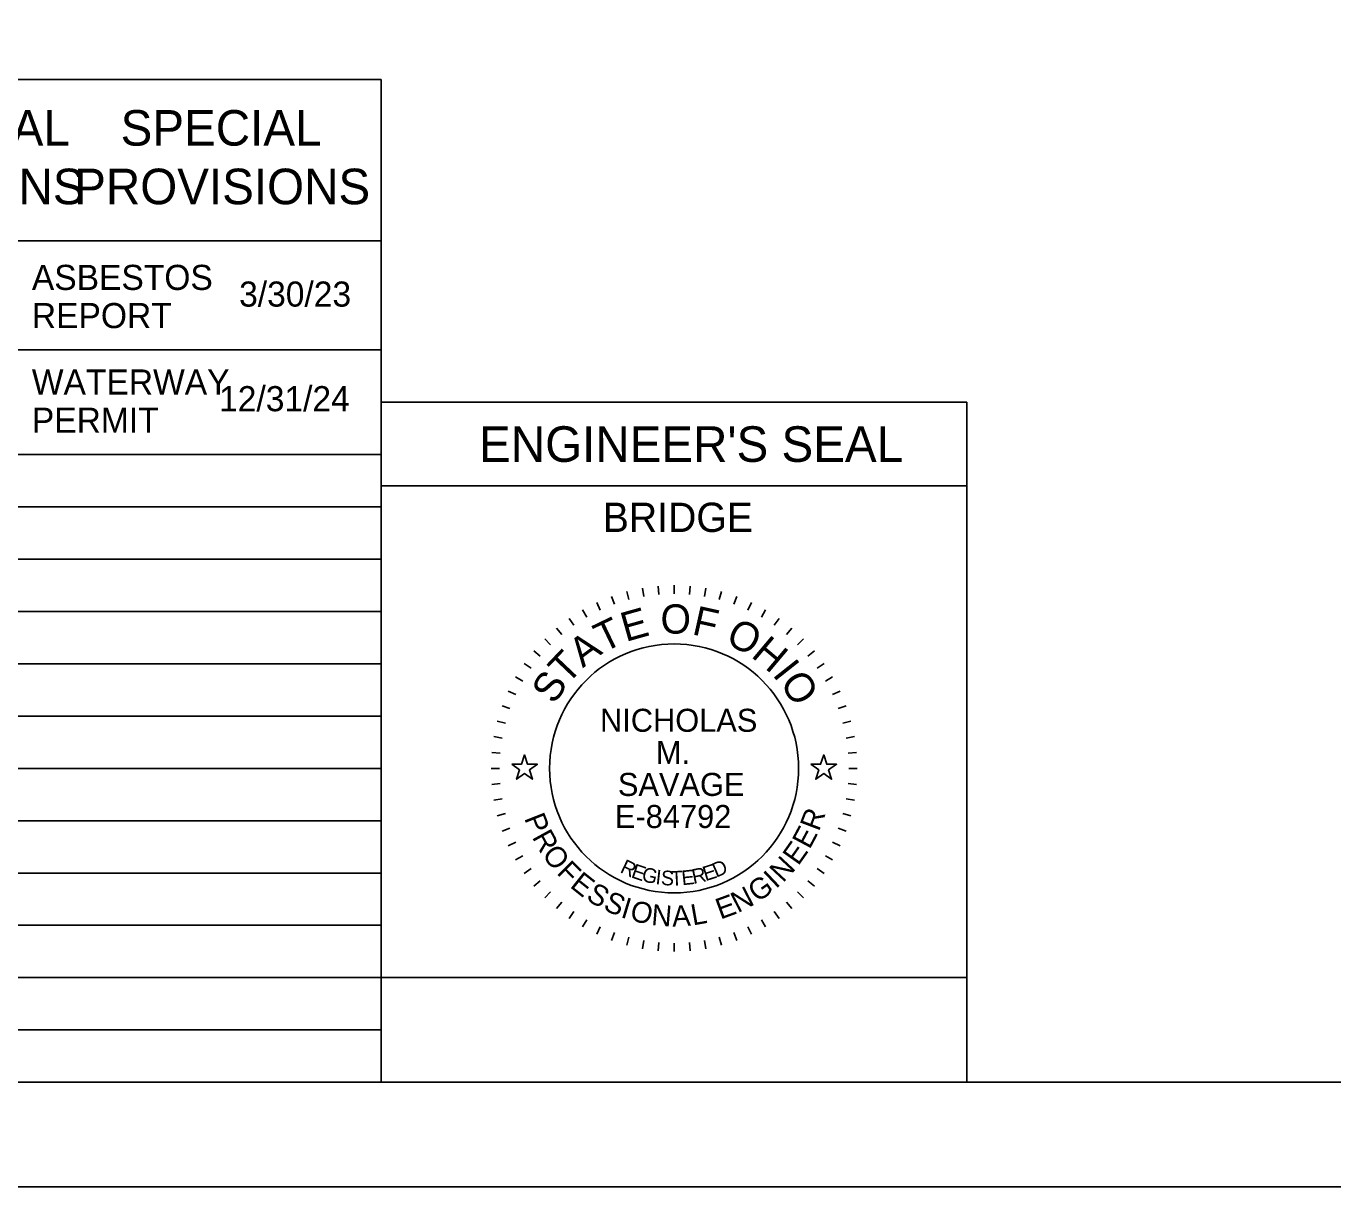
# Model space of a CAD drawing. Extents: x 0 to 34, y 0 to 22.
# Drawn here: x 21.9 to 28.15, y 0 to 5.55 of the extents above; entities that cross this region are included whole.
import ezdxf

# ---------------------------------------------------------------- set-up
doc = ezdxf.new("R2010")
doc.units = 0
for name, color, linetype in [('SH_Border', 7, 'Continuous'), ('SH_Cut_Line', 7, 'Continuous'), ('SH_Data', 7, 'Continuous'), ('SH_Seal', 7, 'Continuous'), ('SH_Text', 7, 'Continuous')]:
    doc.layers.add(name, color=color, linetype=linetype)

msp = doc.modelspace()

# ---------------------------------------------------------------- linework, layer by layer
at = {"layer": 'SH_Border'}
msp.add_lwpolyline([(1.5, 21.5), (33.5, 21.5), (33.5, 0.5), (1.5, 0.5)], close=True, dxfattribs=at)
at = {"layer": 'SH_Cut_Line'}
msp.add_lwpolyline([(0, 0), (34, 0), (34, 22), (0, 22)], close=True, dxfattribs=at)
at = {"layer": 'SH_Data'}
for p, q in [((10.15, 5.2917), (23.6, 5.2917)), ((23.6, 0.5), (23.6, 5.2917)), ((10.15, 4.5209), (23.6, 4.5209)), ((10.15, 4), (23.6, 4)), ((23.6, 0.5), (23.6, 3.75)), ((23.6, 3.75), (26.4, 3.75)), ((26.4, 3.75), (26.4, 0.5)), ((10.15, 3.5), (23.6, 3.5)), ((23.6, 3.35), (26.4, 3.35)), ((10.15, 3.25), (23.6, 3.25)), ((10.15, 3), (23.6, 3)), ((10.15, 2.75), (23.6, 2.75)), ((10.15, 2.5), (23.6, 2.5)), ((10.15, 2.25), (23.6, 2.25)), ((10.15, 2), (23.6, 2)), ((10.15, 1.75), (23.6, 1.75)), ((10.15, 1.5), (23.6, 1.5)), ((10.15, 1.25), (23.6, 1.25)), ((10.15, 1), (23.6, 1)), ((10.15, 0.75), (23.6, 0.75)), ((23.6, 0.5), (26.4, 0.5))]:
    msp.add_line(p, q, dxfattribs=at)
msp.add_lwpolyline([(23.6, 0.5), (23.6, 1), (26.4, 1), (26.4, 0.5)], close=True, dxfattribs=at)
at = {"layer": 'SH_Seal'}
for p, q in [((25, 2.875), (25, 2.835)), ((24.7007, 2.8222), (24.7144, 2.7846)), ((24.7735, 2.8452), (24.7839, 2.8065)), ((24.8481, 2.8617), (24.855, 2.8223)), ((24.9237, 2.8717), (24.9272, 2.8318)), ((25.0763, 2.8717), (25.0728, 2.8318)), ((25.1519, 2.8617), (25.145, 2.8223)), ((25.2265, 2.8452), (25.2161, 2.8065)), ((25.2993, 2.8222), (25.2856, 2.7846)), ((24.5625, 2.7578), (24.5825, 2.7231)), ((24.6302, 2.793), (24.6471, 2.7568)), ((25.3698, 2.793), (25.3529, 2.7568)), ((25.4375, 2.7578), (25.4175, 2.7231)), ((24.4981, 2.7168), (24.5211, 2.684)), ((25.5019, 2.7168), (25.4789, 2.684)), ((24.4376, 2.6703), (24.4633, 2.6396)), ((25.5624, 2.6703), (25.5367, 2.6396)), ((24.3297, 2.5624), (24.3604, 2.5367)), ((24.3813, 2.6187), (24.4096, 2.5904)), ((25.6187, 2.6187), (25.5904, 2.5904)), ((25.6703, 2.5624), (25.6396, 2.5367)), ((24.2832, 2.5019), (24.316, 2.4789)), ((25.7168, 2.5019), (25.684, 2.4789)), ((24.2422, 2.4375), (24.2769, 2.4175)), ((25.7578, 2.4375), (25.7231, 2.4175)), ((24.207, 2.3698), (24.2432, 2.3529)), ((25.793, 2.3698), (25.7568, 2.3529)), ((24.1778, 2.2993), (24.2154, 2.2856)), ((25.8222, 2.2993), (25.7846, 2.2856)), ((24.1548, 2.2265), (24.1935, 2.2161)), ((25.8452, 2.2265), (25.8065, 2.2161)), ((24.1383, 2.1519), (24.1777, 2.145)), ((25.8617, 2.1519), (25.8223, 2.145)), ((24.1283, 2.0763), (24.1682, 2.0728)), ((25.8717, 2.0763), (25.8318, 2.0728)), ((24.125, 2), (24.165, 2)), ((25.875, 2), (25.835, 2)), ((24.1283, 1.9237), (24.1682, 1.9272)), ((25.8717, 1.9237), (25.8318, 1.9272)), ((24.1383, 1.8481), (24.1777, 1.855)), ((25.8617, 1.8481), (25.8223, 1.855)), ((24.1548, 1.7735), (24.1935, 1.7839)), ((25.8452, 1.7735), (25.8065, 1.7839)), ((24.1778, 1.7007), (24.2154, 1.7144)), ((25.8222, 1.7007), (25.7846, 1.7144)), ((24.207, 1.6302), (24.2432, 1.6471)), ((25.793, 1.6302), (25.7568, 1.6471)), ((24.2422, 1.5625), (24.2769, 1.5825)), ((25.7578, 1.5625), (25.7231, 1.5825)), ((24.2832, 1.4981), (24.316, 1.5211)), ((25.7168, 1.4981), (25.684, 1.5211)), ((24.3297, 1.4376), (24.3604, 1.4633)), ((25.6703, 1.4376), (25.6396, 1.4633)), ((24.3813, 1.3813), (24.4096, 1.4096)), ((25.6187, 1.3813), (25.5904, 1.4096)), ((24.4376, 1.3297), (24.4633, 1.3604)), ((24.4981, 1.2832), (24.5211, 1.316)), ((25.5019, 1.2832), (25.4789, 1.316)), ((25.5624, 1.3297), (25.5367, 1.3604)), ((24.5625, 1.2422), (24.5825, 1.2769)), ((25.4375, 1.2422), (25.4175, 1.2769)), ((24.6302, 1.207), (24.6471, 1.2432)), ((24.7007, 1.1778), (24.7144, 1.2154)), ((24.7735, 1.1548), (24.7839, 1.1935)), ((25.2265, 1.1548), (25.2161, 1.1935)), ((25.2993, 1.1778), (25.2856, 1.2154)), ((25.3698, 1.207), (25.3529, 1.2432)), ((24.8481, 1.1383), (24.855, 1.1777)), ((24.9237, 1.1283), (24.9272, 1.1682)), ((25, 1.125), (25, 1.165)), ((25.0763, 1.1283), (25.0728, 1.1682)), ((25.1519, 1.1383), (25.145, 1.1777))]:
    msp.add_line(p, q, dxfattribs=at)
for points in [[(24.2236, 2.02), (24.2705, 2.02), (24.285, 2.0645), (24.2995, 2.02), (24.3464, 2.02), (24.3085, 1.9924), (24.323, 1.9478), (24.285, 1.9754), (24.247, 1.9478), (24.2615, 1.9924)], [(25.6536, 2.02), (25.7005, 2.02), (25.715, 2.0645), (25.7295, 2.02), (25.7764, 2.02), (25.7385, 1.9924), (25.753, 1.9478), (25.715, 1.9754), (25.677, 1.9478), (25.6915, 1.9924)]]:
    msp.add_lwpolyline(points, close=True, dxfattribs=at)
msp.add_circle((25, 2), 0.595, dxfattribs=at)

# ---------------------------------------------------------------- texts
at = {"layer": 'SH_Data'}
for s, height, p in [("ENGINEER'S SEAL", 0.17, (24.0676, 3.465)), ('BRIDGE', 0.14, (24.659, 3.13))]:
    msp.add_text(s, height=height, dxfattribs=at).set_placement(p)
at = {"layer": 'SH_Seal'}
for s, height, rotation, p in [('E', 0.14, 15.75706, (24.7684, 2.6038)), ('O', 0.14, 359.78119, (24.9347, 2.6443)), ('F', 0.14, 347.43619, (25.0811, 2.6417)), ('T', 0.14, 25.71674, (24.6616, 2.5518)), ('O', 0.14, 332.25863, (25.2398, 2.6015)), ('A', 0.14, 36.47472, (24.5634, 2.4781)), ('H', 0.14, 319.91363, (25.3632, 2.5361)), ('T', 0.14, 46.4344, (24.4883, 2.3964)), ('I', 0.14, 308.36695, (25.4665, 2.4483)), ('S', 0.14, 57.19238, (24.4281, 2.3014)), ('O', 0.14, 303.14906, (25.5021, 2.4089)), ('P', 0.1, 291.49398, (24.2823, 1.7621)), ('R', 0.1, 69.23216, (25.6919, 1.6954)), ('R', 0.1, 298.73106, (24.319, 1.6717)), ('E', 0.1, 61.99508, (25.6476, 1.6098)), ('O', 0.1, 306.46664, (24.3655, 1.5883)), ('E', 0.1, 54.75801, (25.5933, 1.5314)), ('R', 0.07, 334.48695, (24.7375, 1.5051)), ('N', 0.1, 47.02243, (25.5202, 1.4508)), ('F', 0.1, 314.7068, (24.4343, 1.4983)), ('E', 0.1, 321.43929, (24.4978, 1.4348)), ('E', 0.07, 341.03996, (24.7906, 1.4801)), ('G', 0.07, 347.47515, (24.8414, 1.4618)), ('I', 0.07, 353.78581, (24.9091, 1.4468)), ('S', 0.07, 356.89262, (24.9358, 1.4429)), ('T', 0.07, 3.00609, (24.9857, 1.4387)), ('E', 0.07, 6.01169, (25.0389, 1.4412)), ('R', 0.07, 11.91844, (25.0925, 1.4474)), ('E', 0.07, 17.68363, (25.1498, 1.4602)), ('D', 0.07, 23.30524, (25.201, 1.477)), ('I', 0.1, 43.28703, (25.4868, 1.4214)), ('S', 0.1, 328.67637, (24.5743, 1.3752)), ('G', 0.1, 35.04687, (25.3981, 1.357)), ('S', 0.1, 335.91345, (24.6564, 1.3266)), ('I', 0.1, 343.15053, (24.7406, 1.2897)), ('E', 0.1, 20.07421, (25.2212, 1.277)), ('N', 0.1, 27.31129, (25.3045, 1.3075)), ('O', 0.1, 346.88592, (24.7839, 1.2751)), ('N', 0.1, 355.12608, (24.8888, 1.2517)), ('A', 0.1, 2.86166, (24.9923, 1.2437)), ('L', 0.1, 10.09874, (25.0894, 1.249))]:
    msp.add_text(s, height=height, rotation=rotation, dxfattribs=at).set_placement(p)
for s, p in [('NICHOLAS', (24.6459, 2.1749)), ('M.', (24.9126, 2.0216)), ('SAVAGE', (24.7313, 1.8684)), ('E-84792', (24.7172, 1.7151))]:
    msp.add_text(s, height=0.11, dxfattribs=at).set_placement(p)
at = {"layer": 'SH_Text'}
for s, height, p in [('SUPPLEMENTAL', 0.17, (20.2925, 4.9763)), ('SPECIAL', 0.17, (22.3542, 4.9763)), ('SPECIFICATIONS', 0.17, (20.2871, 4.6963)), ('PROVISIONS', 0.17, (22.1323, 4.6963)), ('ASBESTOS', 0.12, (21.93, 4.2867)), ('3/30/23', 0.12, (22.9207, 4.207)), ('REPORT', 0.12, (21.93, 4.1042)), ('WATERWAY ', 0.12, (21.93, 3.7867)), ('12/31/24', 0.12, (22.825, 3.707)), ('PERMIT', 0.12, (21.93, 3.6042))]:
    msp.add_text(s, height=height, dxfattribs=at).set_placement(p)

doc.saveas('drawing.dxf')
